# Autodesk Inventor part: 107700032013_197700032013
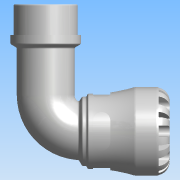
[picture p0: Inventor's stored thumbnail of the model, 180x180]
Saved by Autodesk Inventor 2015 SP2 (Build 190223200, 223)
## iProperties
Created: 2016-12
Part Number: 107700032013_197700032013
Material: PVC-Piping
Description: PLASSON 90° ELBOW WITH MALE INTEGRAL BRASS 32X1.1/4" SERIES 1
Document SubType Name: Modeling
Designer: KIM
Mass: 664.223 g
Surface Area: 733.008 cm^2
Volume: 474.445 cm^3
Density: 1.4 g/cm^3
Appearance: Smooth - White
Author: KIM
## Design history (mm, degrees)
derived "1077.ipt"
feature "Solid1::1077.ipt"
tag "TaggingFeature1"
body "Solid1"
other parameters: "d1" = 22.68, "d2" = 32, "d4" = 58, "d8" = 49.3, "d13" = 7.2, "d14" = 7.2, "d15" = 0, "d17" = 360 deg, "d19" = 8 deg, "d20" = 0.64, "d21" = 0.64, "d22" = 8 deg, "d24" = 0, "d26" = 360 deg, "d33" = 5.8, "d43" = 45.24, "d51" = 0.58, "d54" = 11.2, "d55" = 7.04, "d57" = 14.112, "d58" = 0, "d74" = 0, "d78" = 54, "d82" = 0.64, "d115" = 360 deg, "d207" = 90 deg, "d228" = 9.52, "d247" = 1.16, "d248" = 3.24, "d268" = 27.115, "d269" = 3.24, "d270" = 81, "d276" = 41.91, "d278" = 46.101, "d279" = 83, "d280" = 26, "d281" = 6.2865, "d283" = 37.719, "d286" = 0, "d287" = 0, "d288" = 29.337, "d290" = 3.7605, "d292" = 30 deg, "d294" = 4.191, "d296" = 30 deg, "d_" = 32, "E_" = 58, "l_" = 54, "A_" = 81, "A_1" = 83, "R_" = 41.91, "d9" = 9, "d11" = 58, "d289" = 29.337
